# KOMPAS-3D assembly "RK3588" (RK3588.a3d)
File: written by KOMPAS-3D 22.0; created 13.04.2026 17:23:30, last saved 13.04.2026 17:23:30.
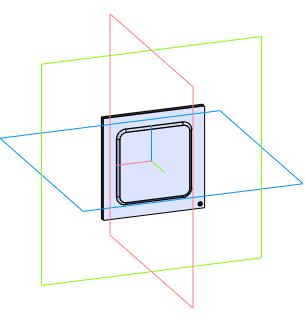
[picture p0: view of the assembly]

Document properties: Автор: Andrey; Полное имя файла: C:\Users\User1\Documents\RK3588.a3d

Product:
- Component [detail]: RK3588_body  | qty 1  | source file: RK3588_body.m3d
- Component [detail]: RK3588_ball  | qty 1088  | source file: RK3588_ball.m3d
- Part/product: RK3588

Referenced files in C:\Users\User1\Documents\: RK3588_body.m3d, RK3588_ball.m3d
